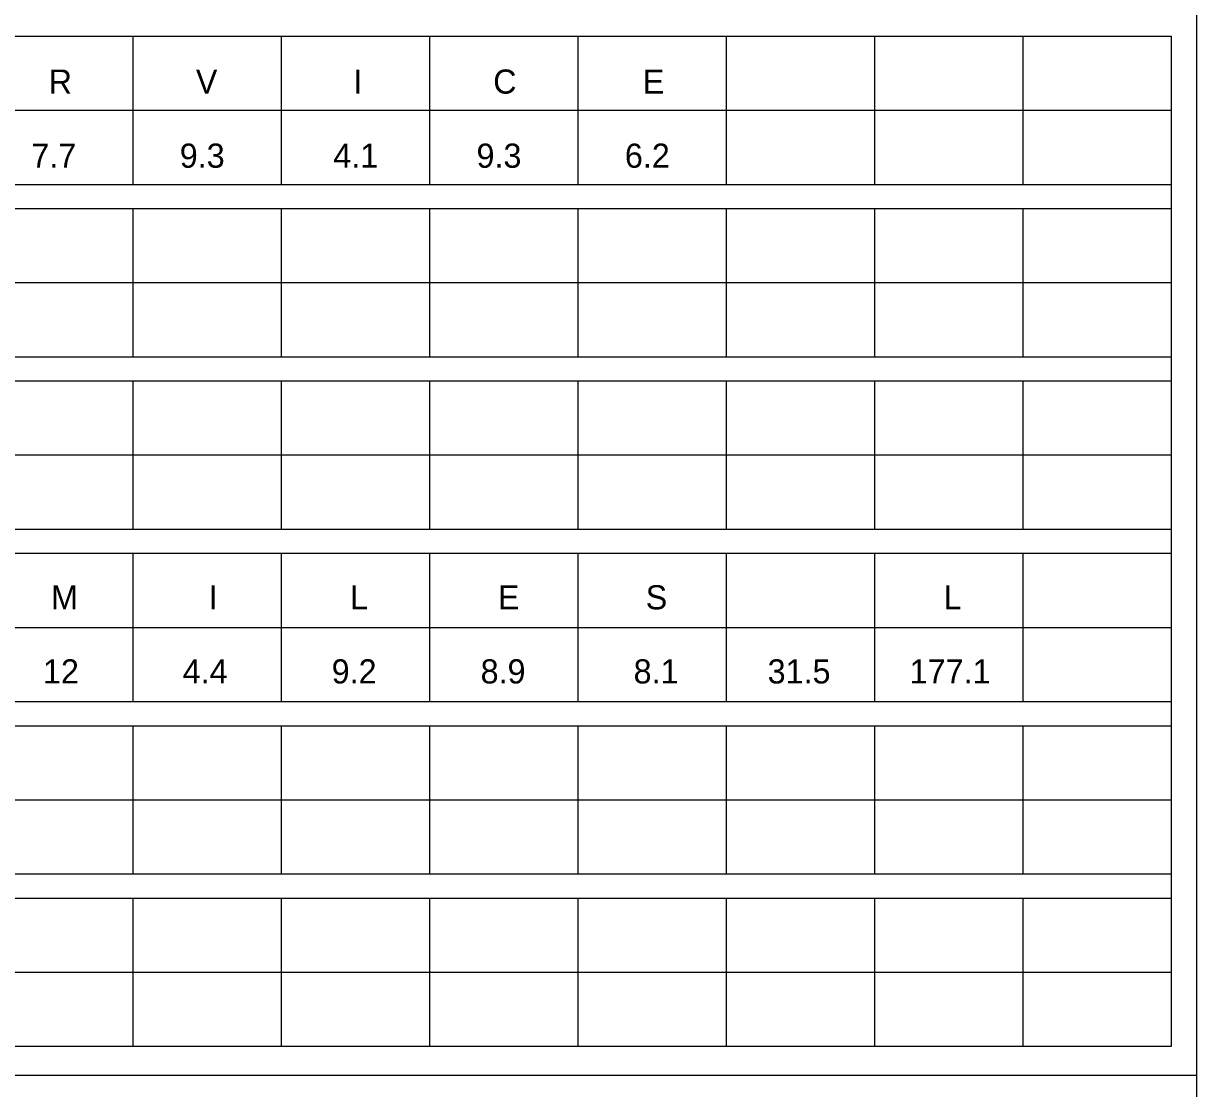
# Model space of a CAD drawing. Extents: x 17890484 to 17890754, y 17897495 to 17897992.
# Drawn here: x 17890540.84 to 17890564.64, y 17897550.71 to 17897572.31 of the extents above; entities that cross this region are included whole.
import ezdxf

# ---------------------------------------------------------------- set-up
doc = ezdxf.new("R2010")
doc.units = 0
doc.layers.add('GSSign', color=7, linetype='Continuous')
doc.layers.add('SheetLinesMisc2_dp', color=7, linetype='Continuous')

msp = doc.modelspace()

# ---------------------------------------------------------------- linework, layer by layer
at = {"layer": 'SheetLinesMisc2_dp'}
for p, q in [((17890564.641, 17897597.808), (17890564.641, 17897504.15)), ((17890490.134, 17897572.057), (17890564.13, 17897572.057)), ((17890543.059, 17897572.057), (17890543.059, 17897569.05)), ((17890546.069, 17897572.057), (17890546.069, 17897569.05)), ((17890549.079, 17897572.057), (17890549.079, 17897569.05)), ((17890552.089, 17897572.057), (17890552.089, 17897569.05)), ((17890555.099, 17897572.057), (17890555.099, 17897569.05)), ((17890558.109, 17897572.057), (17890558.109, 17897569.05)), ((17890561.12, 17897572.057), (17890561.12, 17897569.05)), ((17890564.13, 17897551.569), (17890564.13, 17897572.057)), ((17890490.134, 17897570.554), (17890564.13, 17897570.554)), ((17890490.134, 17897569.05), (17890564.13, 17897569.05)), ((17890490.134, 17897568.56), (17890564.13, 17897568.56)), ((17890543.059, 17897568.56), (17890543.059, 17897565.555)), ((17890546.069, 17897568.56), (17890546.069, 17897565.555)), ((17890549.079, 17897568.56), (17890549.079, 17897565.555)), ((17890552.089, 17897568.56), (17890552.089, 17897565.555)), ((17890555.099, 17897568.56), (17890555.099, 17897565.555)), ((17890558.109, 17897568.56), (17890558.109, 17897565.555)), ((17890561.12, 17897568.56), (17890561.12, 17897565.555)), ((17890490.134, 17897567.057), (17890564.13, 17897567.058)), ((17890490.134, 17897565.555), (17890564.13, 17897565.555)), ((17890490.134, 17897565.064), (17890564.13, 17897565.064)), ((17890543.059, 17897565.064), (17890543.059, 17897562.058)), ((17890546.069, 17897565.064), (17890546.069, 17897562.058)), ((17890549.079, 17897565.064), (17890549.079, 17897562.058)), ((17890552.089, 17897565.064), (17890552.089, 17897562.058)), ((17890555.099, 17897565.064), (17890555.099, 17897562.058)), ((17890558.109, 17897565.064), (17890558.109, 17897562.058)), ((17890561.12, 17897565.064), (17890561.12, 17897562.058)), ((17890490.134, 17897563.561), (17890564.13, 17897563.561)), ((17890490.134, 17897562.058), (17890564.13, 17897562.058)), ((17890490.134, 17897561.568), (17890564.13, 17897561.568)), ((17890543.059, 17897561.568), (17890543.059, 17897558.562)), ((17890546.069, 17897561.568), (17890546.069, 17897558.562)), ((17890549.079, 17897561.568), (17890549.079, 17897558.562)), ((17890552.089, 17897561.568), (17890552.089, 17897558.562)), ((17890555.099, 17897561.568), (17890555.099, 17897558.562)), ((17890558.109, 17897561.568), (17890558.109, 17897558.562)), ((17890561.12, 17897561.568), (17890561.12, 17897558.562)), ((17890490.134, 17897560.065), (17890564.13, 17897560.065)), ((17890490.134, 17897558.562), (17890564.13, 17897558.562)), ((17890490.134, 17897558.071), (17890564.13, 17897558.071)), ((17890543.059, 17897558.071), (17890543.059, 17897555.065)), ((17890546.069, 17897558.071), (17890546.069, 17897555.065)), ((17890549.079, 17897558.071), (17890549.079, 17897555.065)), ((17890552.089, 17897558.071), (17890552.089, 17897555.065)), ((17890555.099, 17897558.071), (17890555.099, 17897555.065)), ((17890558.109, 17897558.071), (17890558.109, 17897555.065)), ((17890561.12, 17897558.071), (17890561.12, 17897555.065)), ((17890490.134, 17897556.569), (17890564.13, 17897556.569)), ((17890490.134, 17897555.065), (17890564.13, 17897555.065)), ((17890490.134, 17897554.575), (17890564.13, 17897554.575)), ((17890543.059, 17897554.575), (17890543.059, 17897551.569)), ((17890546.069, 17897554.575), (17890546.069, 17897551.569)), ((17890549.079, 17897554.575), (17890549.079, 17897551.569)), ((17890552.089, 17897554.575), (17890552.089, 17897551.569)), ((17890555.099, 17897554.575), (17890555.099, 17897551.569)), ((17890558.109, 17897554.575), (17890558.109, 17897551.569)), ((17890561.12, 17897554.575), (17890561.12, 17897551.569)), ((17890490.134, 17897553.073), (17890564.13, 17897553.073)), ((17890490.134, 17897551.569), (17890564.13, 17897551.569)), ((17890489.413, 17897550.979), (17890564.641, 17897550.979))]:
    msp.add_line(p, q, dxfattribs=at)

# ---------------------------------------------------------------- texts
at = {"layer": 'GSSign'}
for s, height, p in [('R', 0.49, (17890541.352, 17897570.89)), ('V', 0.49, (17890544.339, 17897570.89)), ('I', 0.49, (17890547.536, 17897570.89)), ('C', 0.49, (17890550.371, 17897570.89)), ('E', 0.49, (17890553.405, 17897570.89)), ('7.7', 0.4902, (17890541.001, 17897569.387)), ('9.3', 0.4902, (17890544.012, 17897569.387)), ('4.1', 0.4902, (17890547.127, 17897569.387)), ('9.3', 0.4902, (17890550.033, 17897569.387)), ('6.2', 0.4902, (17890553.043, 17897569.387)), ('M', 0.49, (17890541.4, 17897560.43)), ('I', 0.49, (17890544.597, 17897560.43)), ('L', 0.49, (17890547.468, 17897560.43)), ('E', 0.49, (17890550.466, 17897560.43)), ('S', 0.49, (17890553.465, 17897560.43)), ('L', 0.49, (17890559.509, 17897560.43)), ('12', 0.4902, (17890541.237, 17897558.927)), ('4.4', 0.4902, (17890544.072, 17897558.927)), ('9.2', 0.4902, (17890547.094, 17897558.927)), ('8.9', 0.4902, (17890550.116, 17897558.927)), ('8.1', 0.4902, (17890553.22, 17897558.927)), ('31.5', 0.4902, (17890555.939, 17897558.927)), ('177.1', 0.4902, (17890558.821, 17897558.927))]:
    msp.add_text(s, height=height, dxfattribs=at).set_placement(p)

doc.saveas('drawing.dxf')
